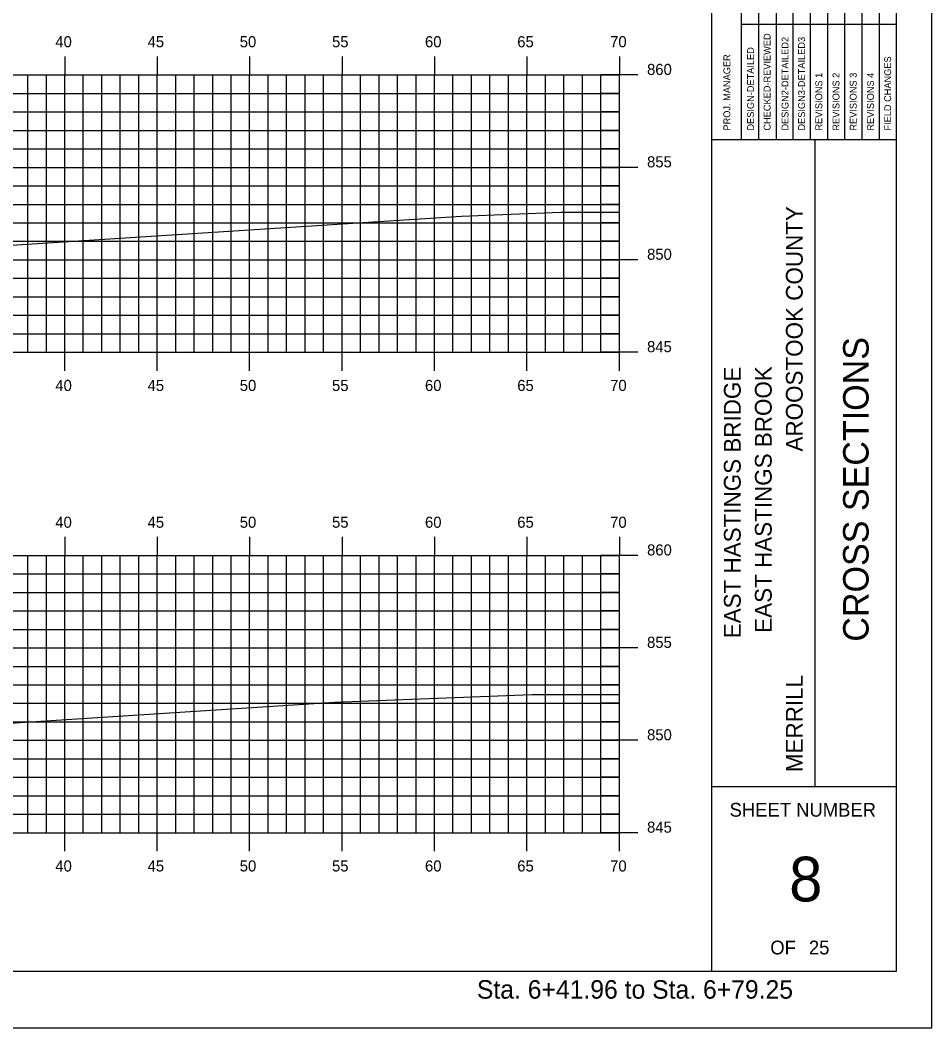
# Model space of a CAD drawing. Extents: x 2193811 to 2194294, y 863888 to 863998.
# Drawn here: x 2194070.8 to 2194120.1, y 863888.4 to 863942.9 of the extents above; entities that cross this region are included whole.
import ezdxf

# ---------------------------------------------------------------- set-up
doc = ezdxf.new("R2010")
doc.units = 0
for name, color, linetype in [('BORDER', 7, 'Continuous'), ('BRIDGE_TITLE', 7, 'Continuous'), ('H_V ANNOTATION', 7, 'Continuous'), ('MAJOR', 7, 'Continuous'), ('MINOR', 7, 'Continuous'), ('PLOT BOUNDARY', 7, 'Continuous'), ('S_Roadway_Centerline', 7, 'Continuous')]:
    doc.layers.add(name, color=color, linetype=linetype)

msp = doc.modelspace()

# ---------------------------------------------------------------- linework, layer by layer
at = {"layer": 'BORDER'}
for p, q in [((2194108.23, 863891.446), (2194108.23, 863996.446)), ((2194108.23, 863936.449), (2194118.23, 863936.449)), ((2194113.821, 863901.449), (2194113.821, 863936.449)), ((2194108.23, 863901.449), (2194118.23, 863901.449))]:
    msp.add_line(p, q, dxfattribs=at)
msp.add_lwpolyline([(2193958.23, 863891.446), (2194118.23, 863891.446), (2194118.23, 863996.446), (2193958.23, 863996.446)], close=True, dxfattribs=at)
for points in [[(2194110.777, 863936.452), (2194110.777, 863953.949)], [(2194111.709, 863953.949), (2194111.709, 863936.452)], [(2194112.641, 863936.452), (2194112.641, 863953.949)], [(2194113.572, 863936.452), (2194113.572, 863953.949)], [(2194114.504, 863936.452), (2194114.504, 863953.949)], [(2194115.436, 863936.452), (2194115.436, 863953.949)], [(2194116.367, 863936.452), (2194116.367, 863953.949)], [(2194117.299, 863936.452), (2194117.299, 863953.949)], [(2194109.846, 863936.452), (2194109.846, 863953.243)], [(2194109.845, 863942.699), (2194118.23, 863942.699)]]:
    msp.add_lwpolyline(points, dxfattribs=at)
at = {"layer": 'MAJOR'}
for p, q in [((2194073.23, 863940.948), (2194073.23, 863939.946)), ((2194078.23, 863940.948), (2194078.23, 863939.946)), ((2194083.23, 863940.948), (2194083.23, 863939.946)), ((2194088.23, 863940.948), (2194088.23, 863939.946)), ((2194093.23, 863940.948), (2194093.23, 863939.946)), ((2194098.23, 863940.948), (2194098.23, 863939.946)), ((2194103.23, 863940.948), (2194103.23, 863939.946)), ((2193963.23, 863939.946), (2194103.23, 863939.946)), ((2193963.23, 863939.946), (2194103.23, 863939.946)), ((2194073.23, 863924.946), (2194073.23, 863939.946)), ((2194078.23, 863924.946), (2194078.23, 863939.946)), ((2194083.23, 863924.946), (2194083.23, 863939.946)), ((2194088.23, 863924.946), (2194088.23, 863939.946)), ((2194093.23, 863924.946), (2194093.23, 863939.946)), ((2194098.23, 863924.946), (2194098.23, 863939.946)), ((2194104.232, 863939.946), (2194102.228, 863939.946)), ((2194103.23, 863924.946), (2194103.23, 863939.946)), ((2194103.23, 863924.946), (2194103.23, 863939.946)), ((2193963.23, 863934.946), (2194103.23, 863934.946)), ((2194104.232, 863934.946), (2194102.228, 863934.946)), ((2193963.23, 863929.946), (2194103.23, 863929.946)), ((2194104.232, 863929.946), (2194102.228, 863929.946)), ((2193963.23, 863924.946), (2194103.23, 863924.946)), ((2194073.23, 863923.944), (2194073.23, 863924.946)), ((2194078.23, 863923.944), (2194078.23, 863924.946)), ((2194083.23, 863923.944), (2194083.23, 863924.946)), ((2194088.23, 863923.944), (2194088.23, 863924.946)), ((2194093.23, 863923.944), (2194093.23, 863924.946)), ((2194098.23, 863923.944), (2194098.23, 863924.946)), ((2194104.232, 863924.946), (2194102.228, 863924.946)), ((2194103.23, 863923.944), (2194103.23, 863924.946)), ((2194073.23, 863914.948), (2194073.23, 863913.946)), ((2194078.23, 863914.948), (2194078.23, 863913.946)), ((2194083.23, 863914.948), (2194083.23, 863913.946)), ((2194088.23, 863914.948), (2194088.23, 863913.946)), ((2194093.23, 863914.948), (2194093.23, 863913.946)), ((2194098.23, 863914.948), (2194098.23, 863913.946)), ((2194103.23, 863914.948), (2194103.23, 863913.946)), ((2193963.23, 863913.946), (2194103.23, 863913.946)), ((2193963.23, 863913.946), (2194103.23, 863913.946)), ((2194073.23, 863898.946), (2194073.23, 863913.946)), ((2194078.23, 863898.946), (2194078.23, 863913.946)), ((2194083.23, 863898.946), (2194083.23, 863913.946)), ((2194088.23, 863898.946), (2194088.23, 863913.946)), ((2194093.23, 863898.946), (2194093.23, 863913.946)), ((2194098.23, 863898.946), (2194098.23, 863913.946)), ((2194104.232, 863913.946), (2194102.228, 863913.946)), ((2194103.23, 863898.946), (2194103.23, 863913.946)), ((2194103.23, 863898.946), (2194103.23, 863913.946)), ((2193963.23, 863908.946), (2194103.23, 863908.946)), ((2194104.232, 863908.946), (2194102.228, 863908.946)), ((2193963.23, 863903.946), (2194103.23, 863903.946)), ((2194104.232, 863903.946), (2194102.228, 863903.946)), ((2193963.23, 863898.946), (2194103.23, 863898.946)), ((2194073.23, 863897.944), (2194073.23, 863898.946)), ((2194078.23, 863897.944), (2194078.23, 863898.946)), ((2194083.23, 863897.944), (2194083.23, 863898.946)), ((2194088.23, 863897.944), (2194088.23, 863898.946)), ((2194093.23, 863897.944), (2194093.23, 863898.946)), ((2194098.23, 863897.944), (2194098.23, 863898.946)), ((2194104.232, 863898.946), (2194102.228, 863898.946)), ((2194103.23, 863897.944), (2194103.23, 863898.946))]:
    msp.add_line(p, q, dxfattribs=at)
at = {"layer": 'MINOR'}
for p, q in [((2194071.23, 863924.946), (2194071.23, 863939.946)), ((2194072.23, 863924.946), (2194072.23, 863939.946)), ((2194074.23, 863924.946), (2194074.23, 863939.946)), ((2194075.23, 863924.946), (2194075.23, 863939.946)), ((2194076.23, 863924.946), (2194076.23, 863939.946)), ((2194077.23, 863924.946), (2194077.23, 863939.946)), ((2194079.23, 863924.946), (2194079.23, 863939.946)), ((2194080.23, 863924.946), (2194080.23, 863939.946)), ((2194081.23, 863924.946), (2194081.23, 863939.946)), ((2194082.23, 863924.946), (2194082.23, 863939.946)), ((2194084.23, 863924.946), (2194084.23, 863939.946)), ((2194085.23, 863924.946), (2194085.23, 863939.946)), ((2194086.23, 863924.946), (2194086.23, 863939.946)), ((2194087.23, 863924.946), (2194087.23, 863939.946)), ((2194089.23, 863924.946), (2194089.23, 863939.946)), ((2194090.23, 863924.946), (2194090.23, 863939.946)), ((2194091.23, 863924.946), (2194091.23, 863939.946)), ((2194092.23, 863924.946), (2194092.23, 863939.946)), ((2194094.23, 863924.946), (2194094.23, 863939.946)), ((2194095.23, 863924.946), (2194095.23, 863939.946)), ((2194096.23, 863924.946), (2194096.23, 863939.946)), ((2194097.23, 863924.946), (2194097.23, 863939.946)), ((2194099.23, 863924.946), (2194099.23, 863939.946)), ((2194100.23, 863924.946), (2194100.23, 863939.946)), ((2194101.23, 863924.946), (2194101.23, 863939.946)), ((2194102.23, 863924.946), (2194102.23, 863939.946)), ((2193963.23, 863938.946), (2194103.23, 863938.946)), ((2194103.23, 863938.946), (2194102.228, 863938.946)), ((2193963.23, 863937.946), (2194103.23, 863937.946)), ((2194103.23, 863937.946), (2194102.228, 863937.946)), ((2193963.23, 863936.946), (2194103.23, 863936.946)), ((2194103.23, 863936.946), (2194102.228, 863936.946)), ((2193963.23, 863935.946), (2194103.23, 863935.946)), ((2194103.23, 863935.946), (2194102.228, 863935.946)), ((2193963.23, 863933.946), (2194103.23, 863933.946)), ((2194103.23, 863933.946), (2194102.228, 863933.946)), ((2193963.23, 863932.946), (2194103.23, 863932.946)), ((2194103.23, 863932.946), (2194102.228, 863932.946)), ((2193963.23, 863931.946), (2194103.23, 863931.946)), ((2194103.23, 863931.946), (2194102.228, 863931.946)), ((2193963.23, 863930.946), (2194103.23, 863930.946)), ((2194103.23, 863930.946), (2194102.228, 863930.946)), ((2193963.23, 863928.946), (2194103.23, 863928.946)), ((2194103.23, 863928.946), (2194102.228, 863928.946)), ((2193963.23, 863927.946), (2194103.23, 863927.946)), ((2194103.23, 863927.946), (2194102.228, 863927.946)), ((2193963.23, 863926.946), (2194103.23, 863926.946)), ((2194103.23, 863926.946), (2194102.228, 863926.946)), ((2193963.23, 863925.946), (2194103.23, 863925.946)), ((2194103.23, 863925.946), (2194102.228, 863925.946)), ((2194071.23, 863898.946), (2194071.23, 863913.946)), ((2194072.23, 863898.946), (2194072.23, 863913.946)), ((2194074.23, 863898.946), (2194074.23, 863913.946)), ((2194075.23, 863898.946), (2194075.23, 863913.946)), ((2194076.23, 863898.946), (2194076.23, 863913.946)), ((2194077.23, 863898.946), (2194077.23, 863913.946)), ((2194079.23, 863898.946), (2194079.23, 863913.946)), ((2194080.23, 863898.946), (2194080.23, 863913.946)), ((2194081.23, 863898.946), (2194081.23, 863913.946)), ((2194082.23, 863898.946), (2194082.23, 863913.946)), ((2194084.23, 863898.946), (2194084.23, 863913.946)), ((2194085.23, 863898.946), (2194085.23, 863913.946)), ((2194086.23, 863898.946), (2194086.23, 863913.946)), ((2194087.23, 863898.946), (2194087.23, 863913.946)), ((2194089.23, 863898.946), (2194089.23, 863913.946)), ((2194090.23, 863898.946), (2194090.23, 863913.946)), ((2194091.23, 863898.946), (2194091.23, 863913.946)), ((2194092.23, 863898.946), (2194092.23, 863913.946)), ((2194094.23, 863898.946), (2194094.23, 863913.946)), ((2194095.23, 863898.946), (2194095.23, 863913.946)), ((2194096.23, 863898.946), (2194096.23, 863913.946)), ((2194097.23, 863898.946), (2194097.23, 863913.946)), ((2194099.23, 863898.946), (2194099.23, 863913.946)), ((2194100.23, 863898.946), (2194100.23, 863913.946)), ((2194101.23, 863898.946), (2194101.23, 863913.946)), ((2194102.23, 863898.946), (2194102.23, 863913.946)), ((2193963.23, 863912.946), (2194103.23, 863912.946)), ((2194103.23, 863912.946), (2194102.228, 863912.946)), ((2193963.23, 863911.946), (2194103.23, 863911.946)), ((2194103.23, 863911.946), (2194102.228, 863911.946)), ((2193963.23, 863910.946), (2194103.23, 863910.946)), ((2194103.23, 863910.946), (2194102.228, 863910.946)), ((2193963.23, 863909.946), (2194103.23, 863909.946)), ((2194103.23, 863909.946), (2194102.228, 863909.946)), ((2193963.23, 863907.946), (2194103.23, 863907.946)), ((2194103.23, 863907.946), (2194102.228, 863907.946)), ((2193963.23, 863906.946), (2194103.23, 863906.946)), ((2194103.23, 863906.946), (2194102.228, 863906.946)), ((2193963.23, 863905.946), (2194103.23, 863905.946)), ((2194103.23, 863905.946), (2194102.228, 863905.946)), ((2193963.23, 863904.946), (2194103.23, 863904.946)), ((2194103.23, 863904.946), (2194102.228, 863904.946)), ((2193963.23, 863902.946), (2194103.23, 863902.946)), ((2194103.23, 863902.946), (2194102.228, 863902.946)), ((2193963.23, 863901.946), (2194103.23, 863901.946)), ((2194103.23, 863901.946), (2194102.228, 863901.946)), ((2193963.23, 863900.946), (2194103.23, 863900.946)), ((2194103.23, 863900.946), (2194102.228, 863900.946)), ((2193963.23, 863899.946), (2194103.23, 863899.946)), ((2194103.23, 863899.946), (2194102.228, 863899.946))]:
    msp.add_line(p, q, dxfattribs=at)
at = {"layer": 'PLOT BOUNDARY'}
msp.add_lwpolyline([(2193950.137, 863888.387), (2194120.137, 863888.387), (2194120.137, 863998.387), (2193950.137, 863998.387)], close=True, dxfattribs=at)
at = {"layer": 'S_Roadway_Centerline'}
for points in [[(2194007.204, 863930.189), (2194016.97, 863932.216), (2194018.864, 863932.405), (2194019.833, 863932.563), (2194020.39, 863932.594), (2194021.489, 863932.677), (2194028.066, 863932.795), (2194033.187, 863932.876), (2194039.712, 863932.827), (2194044.659, 863932.763), (2194049.894, 863932.607), (2194049.898, 863932.607), (2194049.904, 863932.606), (2194057.431, 863932.047), (2194060.719, 863930.654), (2194063.5, 863929.453), (2194064.503, 863929.448), (2194065.709, 863929.388), (2194067.87, 863930.316), (2194069.789, 863930.696), (2194094.683, 863932.303), (2194100.066, 863932.516), (2194103.23, 863932.52)], [(2194055.831, 863906.258), (2194060.848, 863904.133), (2194061.992, 863903.639), (2194063.508, 863903.631), (2194064.033, 863903.605), (2194064.974, 863904.009), (2194068.845, 863904.776), (2194087.811, 863906), (2194098.514, 863906.424), (2194103.23, 863906.43)]]:
    msp.add_lwpolyline(points, dxfattribs=at)

# ---------------------------------------------------------------- texts
at = {"layer": 'BORDER'}
for s, height, rotation, p in [('CHECKED-REVIEWED', 0.37275, 90, (2194111.411, 863936.937)), ('DESIGN2-DETAILED2', 0.37275, 90, (2194112.38, 863936.937)), ('DESIGN3-DETAILED3', 0.37275, 90, (2194113.274, 863936.937)), ('DESIGN-DETAILED', 0.37275, 90, (2194110.516, 863936.937)), ('PROJ. MANAGER', 0.37275, 90, (2194109.234, 863936.937)), ('FIELD CHANGES', 0.37275, 90, (2194117.933, 863936.937)), ('REVISIONS 1', 0.37275, 90, (2194114.206, 863936.937)), ('REVISIONS 2', 0.37275, 90, (2194115.138, 863936.937)), ('REVISIONS 3', 0.37275, 90, (2194116.069, 863936.937)), ('REVISIONS 4', 0.37275, 90, (2194117.001, 863936.937)), ('CROSS SECTIONS', 1.37787, 90, (2194116.714, 863909.283)), ('SHEET NUMBER', 0.74527, 360, (2194109.195, 863899.812)), ('8', 2.419, 360, (2194112.417, 863895.228)), ('OF', 0.7453, 360, (2194111.397, 863892.359)), ('25', 0.7453, 360, (2194113.486, 863892.359))]:
    msp.add_text(s, height=height, rotation=rotation, dxfattribs=at).set_placement(p)
at = {"layer": 'BRIDGE_TITLE'}
for s, height, p in [('AROOSTOOK COUNTY', 0.90716, (2194113.15, 863919.571)), ('EAST HASTINGS BRIDGE', 0.90716, (2194109.796, 863909.466)), ('EAST HASTINGS BROOK', 0.90716, (2194111.473, 863909.763)), ('MERRILL', 0.9072, (2194113.15, 863902.222))]:
    msp.add_text(s, height=height, rotation=90, dxfattribs=at).set_placement(p)
at = {"layer": 'H_V ANNOTATION'}
for s, height, p in [('40', 0.6, (2194072.716, 863941.446)), ('45', 0.6, (2194077.708, 863941.446)), ('50', 0.6, (2194082.694, 863941.446)), ('55', 0.6, (2194087.686, 863941.446)), ('60', 0.6, (2194092.716, 863941.446)), ('65', 0.6, (2194097.708, 863941.446)), ('70', 0.6, (2194102.732, 863941.446)), ('860', 0.6, (2194104.73, 863939.946)), ('855', 0.6, (2194104.73, 863934.946)), ('850', 0.6, (2194104.73, 863929.946)), ('845', 0.6, (2194104.73, 863924.946)), ('40', 0.6, (2194072.716, 863922.846)), ('45', 0.6, (2194077.708, 863922.846)), ('50', 0.6, (2194082.694, 863922.846)), ('55', 0.6, (2194087.686, 863922.846)), ('60', 0.6, (2194092.716, 863922.846)), ('65', 0.6, (2194097.708, 863922.846)), ('70', 0.6, (2194102.732, 863922.846)), ('40', 0.6, (2194072.716, 863915.446)), ('45', 0.6, (2194077.708, 863915.446)), ('50', 0.6, (2194082.694, 863915.446)), ('55', 0.6, (2194087.686, 863915.446)), ('60', 0.6, (2194092.716, 863915.446)), ('65', 0.6, (2194097.708, 863915.446)), ('70', 0.6, (2194102.732, 863915.446)), ('860', 0.6, (2194104.73, 863913.946)), ('855', 0.6, (2194104.73, 863908.946)), ('850', 0.6, (2194104.73, 863903.946)), ('845', 0.6, (2194104.73, 863898.946)), ('40', 0.6, (2194072.716, 863896.846)), ('45', 0.6, (2194077.708, 863896.846)), ('50', 0.6, (2194082.694, 863896.846)), ('55', 0.6, (2194087.686, 863896.846)), ('60', 0.6, (2194092.716, 863896.846)), ('65', 0.6, (2194097.708, 863896.846)), ('70', 0.6, (2194102.732, 863896.846)), ('Sta. 6+41.96 to Sta. 6+79.25', 1.0002, (2194095.523, 863889.966))]:
    msp.add_text(s, height=height, dxfattribs=at).set_placement(p)

doc.saveas('drawing.dxf')
